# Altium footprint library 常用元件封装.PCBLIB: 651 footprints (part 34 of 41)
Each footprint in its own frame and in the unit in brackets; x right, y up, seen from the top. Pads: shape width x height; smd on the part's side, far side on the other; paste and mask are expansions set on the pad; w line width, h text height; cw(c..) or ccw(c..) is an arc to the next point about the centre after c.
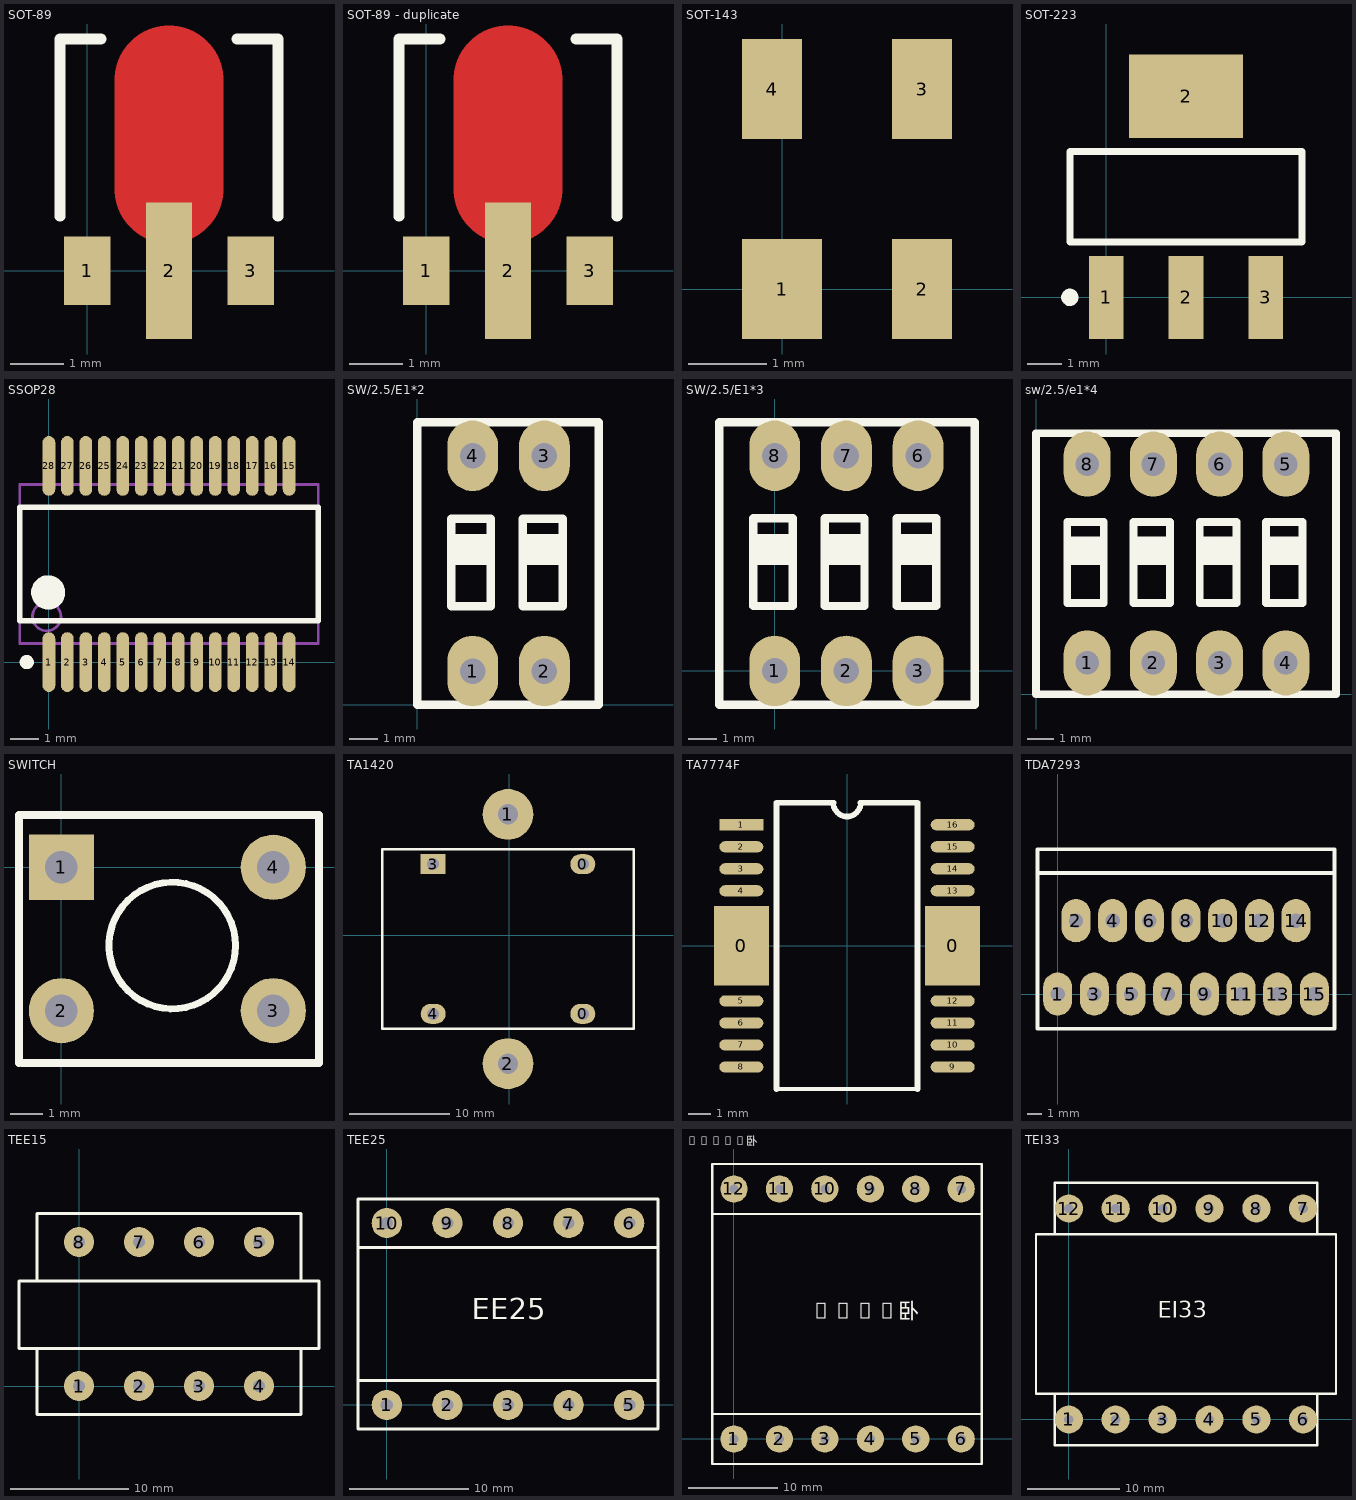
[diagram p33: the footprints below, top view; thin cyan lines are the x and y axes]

## SOT-89 [mil]
pads (3):
  rect 34x50 smd: 1(0,0) 3(120,0)
  rect 34x100 smd: 2(60,0)
TopLayer:
  lines w80: 60,60 60,140
TopOverlay:
  lines w8: -20,40 -20,170 10,170 ; 110,170 140,170 140,40

## SOT-89 - duplicate [mil]
pads (3):
  rect 34x50 smd: 1(0,0) 3(120,0)
  rect 34x100 smd: 2(60,0)
TopLayer:
  lines w80: 60,60 60,140
TopOverlay:
  lines w8: -20,40 -20,170 10,170 ; 110,170 140,170 140,40

## SOT-143 [mil]
pads (4):
  rect 40x50 smd: 1(0,0)
  rect 30x50 smd: 2(70,0) 3(70,100) 4(-5,100)

## SOT-223 [mm] "SOT223, 4-Leads, Body 6.7x7.3mm (max), Pitch 2.30mm, IPC Medium Density"
height 1.8
pads (4):
  rect 1x2.4 smd: 1(0,0) 2(2.3,0) 3(4.6,0)
  rect 3.3x2.4 smd: 2(2.3,5.8)
TopOverlay:
  circle w0.25: c-1.05,0 r0.125
  lines w0.2: -1.05,1.6 -1.05,4.2 5.65,4.2 5.65,1.6 -1.05,1.6

## SSOP28 [mm] "SSOP, 28-Leads, 10.5x5.6mm (max), 0.65mm"
height 2
pads (28):
  oval 0.45x2.1 smd: 1(0,0) 2(0.65,0) 3(1.3,0) 4(1.95,0) 5(2.6,0) 6(3.25,0) 7(3.9,0) 8(4.55,0) 9(5.2,0) 10(5.85,0) 11(6.5,0) 12(7.15,0) 13(7.8,0) 14(8.45,0) 15(8.45,6.9) 16(7.8,6.9) 17(7.15,6.9) 18(6.5,6.9) 19(5.85,6.9) 20(5.2,6.9) 21(4.55,6.9) 22(3.9,6.9) 23(3.25,6.9) 24(2.6,6.9) 25(1.95,6.9) 26(1.3,6.9) 27(0.65,6.9) 28(0,6.9)
TopOverlay:
  circle w0.25: c-0.775,0 r0.125
  circle w0.6: c-0.025,2.45 r0.3
  lines w0.2: -1.025,1.45 9.475,1.45 9.475,5.45 -1.025,5.45 -1.025,1.45
Mechanical13:
  circle w0.1: c-0.075,1.6 r0.5
  lines w0.1: -1.025,0.65 9.475,0.65 9.475,6.25 -1.025,6.25 -1.025,0.65

## SW/2.5/E1*2 [mm]
pads (4):
  oval 1.8x2.5 hole 0.9: 1(1.96,1.2) 2(4.5,1.2) 3(4.5,8.82) 4(1.96,8.82)
TopOverlay:
  lines w0.3: 1.2,5.1 2.6,5.1 ; 1.2,5.4 2.5,5.4 ; 1.2,5.6 2.6,5.6 ; 1.2,5.9 2.5,5.9 ; 3.74,5.4 5.04,5.4 ; 3.74,5.6 5.14,5.6 ; 3.74,5.9 5.04,5.9 ; 0,0 0,10 6.42,10 6.42,0 0,0 ; 1.2,3.5 1.2,6.6 2.6,6.6 2.6,3.5 1.2,3.5 ; 3.74,3.5 3.74,6.6 5.14,6.6 5.14,3.5 3.74,3.5 ; 3.74,5.1 5.14,5.1 3.74,5.1
BottomOverlay:
  rectangle: 0.8,-0.32 5.62,2.68
  rectangle: 0.8,7.3 5.62,10.3
  lines w0.3: 5.6,7.3 0.8,7.3 0.8,10.3 5.62,10.3 5.62,7.3 ; 0.8,-0.32 0.8,2.68 5.62,2.68 5.62,-0.32 0.8,-0.32

## SW/2.5/E1*3 [mm]
pads (6):
  oval 1.8x2.5 hole 0.9: 1(0,0) 2(2.54,0) 3(5.08,0) 6(5.08,7.62) 7(2.54,7.62) 8(0,7.62)
TopOverlay:
  lines w0.3: -0.76,3.9 0.64,3.9 ; -0.76,4.2 0.54,4.2 ; -0.76,4.4 0.64,4.4 ; -0.76,4.7 0.54,4.7 ; 1.78,4.2 3.08,4.2 ; 1.78,4.4 3.18,4.4 ; 1.78,4.7 3.08,4.7 ; 4.32,4.2 5.62,4.2 ; 4.32,4.4 5.72,4.4 ; 4.32,4.7 5.62,4.7 ; 7.075,-1.2 -1.96,-1.2 -1.96,8.8 7.075,8.8 ; 7.08,-1.2 7.08,8.8 ; -0.76,2.3 0.64,2.3 0.64,5.4 -0.76,5.4 -0.76,2.3 ; 1.78,2.3 3.18,2.3 3.18,5.4 1.78,5.4 1.78,2.3 ; 1.78,3.9 3.18,3.9 1.78,3.9 ; 4.32,2.3 5.72,2.3 5.72,5.4 4.32,5.4 4.32,2.3 ; 4.32,3.9 5.72,3.9 4.32,3.9
BottomOverlay:
  rectangle: -1.16,-1.52 6.275,1.475
  rectangle: -1.16,6.1 6.25,9.1
  lines w0.3: -1.16,-1.52 6.275,-1.525 6.275,1.475 -1.16,1.48 -1.16,-1.52 ; -1.16,6.1 6.25,6.1 6.25,9.1 -1.16,9.1 -1.16,6.1

## sw/2.5/e1*4 [mm]
pads (8):
  oval 1.8x2.5 hole 0.9: 1(1.96,1.2) 2(4.5,1.2) 3(7.04,1.2) 4(9.58,1.2) 5(9.58,8.82) 6(7.04,8.82) 7(4.5,8.82) 8(1.96,8.82)
TopOverlay:
  lines w0.3: 1.2,5.1 2.6,5.1 ; 1.2,5.4 2.5,5.4 ; 1.2,5.6 2.6,5.6 ; 1.2,5.9 2.5,5.9 ; 3.74,5.4 5.04,5.4 ; 3.74,5.6 5.14,5.6 ; 3.74,5.9 5.04,5.9 ; 6.28,5.4 7.58,5.4 ; 6.28,5.6 7.68,5.6 ; 6.28,5.9 7.58,5.9 ; 8.82,5.4 10.12,5.4 ; 8.82,5.6 10.22,5.6 ; 8.82,5.9 10.12,5.9 ; 0,0 0,10 11.5,10 11.5,0 0,0 ; 1.2,3.5 1.2,6.6 2.6,6.6 2.6,3.5 1.2,3.5 ; 3.74,3.5 3.74,6.6 5.14,6.6 5.14,3.5 3.74,3.5 ; 3.74,5.1 5.14,5.1 3.74,5.1 ; 6.28,3.5 6.28,6.6 7.68,6.6 7.68,3.5 6.28,3.5 ; 6.28,5.1 7.68,5.1 6.28,5.1 ; 8.82,3.5 8.82,6.6 10.22,6.6 10.22,3.5 8.82,3.5 ; 8.82,5.1 10.22,5.1 8.82,5.1
BottomOverlay:
  rectangle: 0.8,7.3 10.7,10.3
  rectangle: 0.8,-0.32 10.7,2.68
  lines w0.3: 0.8,-0.32 0.8,2.68 10.7,2.68 10.7,-0.32 0.8,-0.32 ; 0.8,7.3 0.8,10.3 10.7,10.3 10.7,7.3 0.8,7.3

## SWITCH [mm]
pads (4):
  rect 2x2 hole 1: 1(0,0)
  round 2 hole 1: 2(0,-4.4) 3(6.5,-4.4) 4(6.5,0)
TopOverlay:
  circle w0.212: c3.4,-2.4 r1.942
  lines w0.254: -1.3,-6 -1.3,1.6 7.9,1.6 7.9,-6 -1.2,-6

## TA1420 [mm]
pads (6):
  oval 2.5x2 hole 1.2: 0(7.38,-7.888) 0(7.38,7.112) 4(-7.62,-7.888)
  round 5.08 hole 2.032: 1(-0.12,12.112) 2(-0.12,-12.888)
  rect 2.5x2 hole 1.2: 3(-7.62,7.112)
TopOverlay:
  lines w0.254: -1.92,8.612 12.48,8.612 12.48,-9.388 -12.72,-9.388 -12.72,8.612 -0.22,8.612

## TA7774F [mm]
pads (18):
  rect 2.5x3.6 smd: 0(-4.8,0) 0(4.8,0)
  rect 2x0.508 smd: 1(-4.8,5.5)
  oval 2x0.508 smd: 2(-4.8,4.5) 3(-4.8,3.5) 4(-4.8,2.5) 5(-4.8,-2.5) 6(-4.8,-3.5) 7(-4.8,-4.5) 8(-4.8,-5.5) 9(4.8,-5.5) 10(4.8,-4.5) 11(4.8,-3.5) 12(4.8,-2.5) 13(4.8,2.5) 14(4.8,3.5) 15(4.8,4.5) 16(4.8,5.5)
TopOverlay:
  lines w0.2: -3.2,-6.5 3.2,-6.5
  lines w0.254: -3.2,-6.5 -3.2,6.5 -0.6,6.5 ; -0.625,6.5 ccw(c0,6.5) 0.625,6.5 ; 0.6,6.5 3.2,6.5 3.2,-6.5

## TDA7293 [mm] "集成功放"
height 20
pads (15):
  oval 2x3 hole 1: 1(0,0) 2(1.27,5.08) 3(2.54,0) 4(3.81,5.08) 5(5.08,0) 6(6.35,5.08) 7(7.62,0) 8(8.89,5.08) 9(10.16,0) 10(11.43,5.08) 11(12.7,0) 12(13.97,5.08) 13(15.24,0) 14(16.51,5.08) 15(17.78,0)
TopOverlay:
  lines w0.254: -1.397,8.382 19.177,8.382 ; -1.397,-2.413 19.177,-2.413 19.177,10.033 -1.397,10.033 -1.397,-2.413

## TEE15 [mil]
pads (8):
  round 100 hole 40: 1(0,0) 2(200,0) 3(400,0) 4(600,0) 5(600,480) 6(400,480) 7(200,480) 8(0,480)
TopOverlay:
  lines w10: -200,240 -200,125 ; -140,125 -140,-95 740,-95 740,125 ; -140,350 -140,575 740,575 740,350 ; -200,125 -200,350 800,350 800,125 -200,125

## TEE25 [mil]
pads (10):
  round 100 hole 40: 1(0,0) 2(200,0) 3(400,0) 4(600,0) 5(800,0) 6(800,600) 7(600,600) 8(400,600) 9(200,600) 10(0,600)
TopOverlay:
  lines w10: -95,80 895,80 ; -95,520 895,520 ; -95,-80 895,-80 895,680 -95,680 -95,-80
  text "EE25" at 280,260 h120

## TEI30卧 [mil] "EI30卧  34mmX30mm  12P"
height 1023.62
pads (12):
  round 120 hole 40: 1(0,0) 2(200,0) 3(400,0) 4(600,0) 5(800,0) 6(1000,0) 7(1000,1100) 8(800,1100) 9(600,1100) 10(400,1100) 11(200,1100) 12(0,1100)
TopOverlay:
  lines w10: -95,110 -95,-110 1090,-110 1090,110 ; -95,110 1090,110 ; -95,110 -95,990 ; -95,990 -95,1210 1090,1210 1090,990 ; -95,990 1090,990 ; 1090,110 1090,990
  text "EI30卧" at 335,505 h120

## TEI33 [mil] "EI33"
pads (12):
  round 120 hole 40: 1(0,0) 2(200,0) 3(400,0) 4(600,0) 5(800,0) 6(1000,0) 7(1000,900) 8(800,900) 9(600,900) 10(400,900) 11(200,900) 12(0,900)
TopOverlay:
  lines w10: -60,110 -60,-110 1060,-110 1060,110 ; -60,790 -60,1010 1060,1010 1060,790 ; -140,110 1140,110 1140,790 -140,790 -140,110
  text "EI33" at 380,410 h120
